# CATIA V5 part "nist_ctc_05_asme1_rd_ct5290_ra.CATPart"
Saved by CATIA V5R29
Part number: CTC_05_ASME1_C29_RC
Revision: C
Nomenclature: Complex Test Case 5
Property "Modeled By": "Rich Eckenrode, RECON-Services.com - Revised by DS"
Property "CAGE Code": "64JW1"
Property "Company": "RECON Services Incorporated"
Bounding box of the stored display mesh (mm): x -263.525 to 263.525, y -279.4 to 279.4, z 0 to 482.6
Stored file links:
  E:\users\dgn\TPS V5\Import-export annotations\Step\PMI representation 2015\NIST UC\CTC\nist_ctc_05_asme1_ct5210_rc - V5R29.CATPart
  E:\users\dgn\TPS V5\Import-export annotations\Step\PMI representation 2015\NIST UC\CTC\nist_ctc_05_asme1_ct5210_rc.CATPart
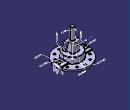
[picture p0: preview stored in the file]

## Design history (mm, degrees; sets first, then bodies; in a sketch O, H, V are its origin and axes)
TTRSSet1
AxisSystem1: origin (0, 0, 0), X (1, 0, 0), Y (0, 1, 0), Z (0, 0, 1)
f4a2d38f3ddc11d3a929006094b99c4b_11 "CATTPSSet"
Set1 "MBD_A"
  Line1: type PtPt, FirstPoint Point2, SecondPoint Point1
  Fill1: Boundary Sketch17
Set2 "MBD_B"
  Fill2: Boundary Sketch18
Body1 (main body)
  Sketch1 on xy-plane, origin (0, 0, 0), H (1, 0, 0), V (0, 1, 0)
    arc A1 centre (0, 0) radius 279.4 from (263.525, 92.8382) to (-263.525, 92.8382) ccw
    line L1 (263.525, 92.8382) -> (263.525, -92.8382)
    line L2 (-263.525, -92.8382) -> (-263.525, 92.8382)
    arc A2 centre (0, 0) radius 279.4 from (-263.525, -92.8382) to (263.525, -92.8382) ccw
    radius A1 = 279.4
    distance L1 L2 = 527.05
    distance L2 V = 263.525
    vertical: L1 V, L2 V
    coincidence: A1 A2
  Pad1: profile Sketch1, direction (0, 0, 1), length 25.4
  Sketch2 on end face of Pad1, origin (0, 0, 25.4), H (1, 0, 0), V (0, 1, 0)
    circle A1 centre (0, 0) radius 152.4
    radius A1 = 152.4
  Pad2: profile Sketch2, direction (0, 0, 1), length 101.6
  Sketch3 on face of Pad1 from Sketch1.L1, origin (263.525, 0, 0), H (0, 1, 0), V (0, 0, 1)
    construction line L1 (0, 195.9632) -> (0, -179.8906)
    point P1 (0, 195.9632)
    construction line L2 (-120.3979, -146.05) -> (120.3979, -146.05)
    arc A1 centre (0, -146.05) radius 203.2 from (69.85, 44.7672) to (32.0282, 54.61) ccw
    point P5 (0, -146.05)
    line L3 (69.85, 44.7672) -> (69.85, 25.4)
    line L4 (-69.85, 44.7672) -> (-69.85, 25.4)
    projected line E1 (-92.8382, 25.4) -> (92.8382, 25.4) from edge [face of Pad1 from Sketch1.L1 | end face of Pad1]
    projected line E2 (-69.85, 25.4) -> (69.85, 25.4) from edge [face of Pad1 from Sketch1.L1 | end face of Pad1]
    line L5 (32.0282, 54.61) -> (-32.0282, 54.61)
    arc A2 centre (0, -146.05) radius 203.2 from (-32.0282, 54.61) to (-69.85, 44.7672) ccw
    distance H L2 = 146.05
    radius A1 = 203.2
    distance L3 L4 = 139.7
    distance L3 L1 = 69.85
    distance L5 E1 = 29.21
    distance P5 L1 = 0
    coincidence: P1 V, A1 A2
    vertical: L1 V, L3 V, L4 V
    horizontal: L2 H, L5 H
    midpoint: P5 L2
  Pad3: profile Sketch3, direction (-1, 0, 0), length 527.05
  Sketch4 on face of Pad3 from Sketch3.L5, origin (0, 0, 54.61), H (1, 0, 0), V (0, 1, 0)
    axis line L1 (333.3573, 0) -> (-349.9817, 0)
    point P1 (333.3573, 0)
    arc A1 centre (203.2, 0) radius 19.05 from (203.2, 19.05) to (203.2, -19.05) ccw
    point P3 (203.2, 0)
    arc A2 centre (-203.2, 0) radius 19.05 from (-203.2, -19.05) to (-203.2, 19.05) ccw
    point P4 (-203.2, 0)
    line L2 (203.2, 19.05) -> (302.0185, 19.05)
    line L3 (302.0185, 19.05) -> (302.0185, -19.05)
    line L4 (302.0185, -19.05) -> (203.2, -19.05)
    line L5 (-203.2, 19.05) -> (-294.9477, 19.05)
    line L6 (-294.9477, 19.05) -> (-294.9477, -19.05)
    line L7 (-294.9477, -19.05) -> (-203.2, -19.05)
    distance L5 L7 = 38.1
    distance L1 L5 = 19.05
    distance V P4 = 203.2
    distance P3 V = 203.2
    coincidence: P1 H, P3 L1, P4 L1, L5 L2, L7 L4
    horizontal: L1 H, L2 H, L4 H, L5 H, L7 H
    vertical: L3 V, L6 V
    tangency: L5 A2, A1 L2
  Pocket1: profile Sketch4, direction (0, 0, -1), length 8.89
  Sketch5 on end face of Pocket1, origin (0, 0, 45.72), H (1, 0, 0), V (0, 1, 0)
    axis line L1 (321.9499, 0) -> (-320.0091, 0)
    point P1 (321.9499, 0)
    reference projected arc E1 centre (203.2, 0) radius 19.05 from (203.2, 19.05) to (203.2, -19.05) ccw from edge [face of Pad3 from Sketch3.L5 | face of Pocket1 from Sketch4.A1]
    point P5 (203.2, 0)
    reference projected arc E2 centre (-203.2, 0) radius 19.05 from (-203.2, -19.05) to (-203.2, 19.05) ccw from edge [face of Pad3 from Sketch3.L5 | face of Pocket1 from Sketch4.A2]
    point P8 (-203.2, 0)
    point P9 (234.95, 0)
    point P10 (-234.95, 0)
    distance P5 P9 = 31.75
    distance P8 P10 = 31.75
    coincidence: P1 H, P9 L1, P10 L1
    horizontal: L1 H
    concentricity: P5 E1, P8 E2
  Sketch6 on end face of Pocket1, origin (234.95, 0, 45.72), H (1, 0, 0), V (0, 1, 0)
    point P1 (0, 0)
    reference projected point E1 (0, 0) from Sketch5.P9
    coincidence: E1 P1
  Hole1: placed by Sketch6, at (234.95, 0, 45.72) direction (0, 0, -1), diameter 7.9375, depth 30.48, V-bottom angle 118, threaded, thread diameter 9.525, thread depth 25.4, pitch 1.5875
  UserPattern1: of Hole1, copies 4, at the points of Sketch5
  Sketch7 on start face of Pad1, origin (0, 0, 0), H (1, 0, 0), V (0, -1, 0)
    circle A1 centre (0, 0) radius 127
    radius A1 = 127
  Pocket2: profile Sketch7, direction (0, 0, 1), length 101.6
  Sketch8 on end face of Pad1, origin (0, 0, 25.4), H (1, 0, 0), V (0, 1, 0)
    construction line L1 (331.5002, 0) -> (-339.96, 0)
    point P1 (331.5002, 0)
    axis line L2 (0, 335.6521) -> (0, -346.3045)
    point P3 (0, 335.6521)
    construction circle A1 centre (0, 0) radius 222.25
    point P5 (0, 222.25)
    point P6 (0, -222.25)
    point P7 (111.1128, -192.4812)
    point P8 (192.4741, -111.125)
    point P9 (-111.1128, -192.4812)
    point P10 (-192.4741, -111.125)
    point P11 (-192.4741, 111.125)
    point P12 (-111.1128, 192.4812)
    point P13 (111.1128, 192.4812)
    point P14 (192.4741, 111.125)
    radius A1 = 222.25
    distance L1 P14 = 111.125
    distance P8 L1 = 111.125
    distance P7 L1 = 192.4812
    distance P13 L1 = 192.4812
    distance P9 L1 = 192.4812
    distance P10 L1 = 111.125
    distance P11 L1 = 111.125
    distance P12 L1 = 192.4812
    coincidence: P1 H, P3 V, P5 A1, P5 L2, P6 A1, P6 L2, P7 A1, P8 A1, P9 A1, P10 A1, P11 A1, P12 A1, P13 A1, P14 A1
    horizontal: L1 H
    vertical: L2 V
  Sketch9 on end face of Pad1, origin (192.4741, -111.125, 25.4), H (1, 0, 0), V (0, 1, 0)
    point P1 (0, 0)
    reference projected point E1 (0, 0) from Sketch8.P8
    coincidence: E1 P1
  Hole2: placed by Sketch9, at (192.4741, -111.125, 25.4) direction (0, 0, -1), diameter 19.05, through (limit type 3), counterbore diameter 38.1, counterbore depth 12.7
  UserPattern2: of Hole2, copies 10, at the points of Sketch8
  Sketch10 on end face of Pad2, origin (0, 0, 127), H (1, 0, 0), V (0, 1, 0)
    construction line L1 (288.441, 0) -> (-310.0968, 0)
    point P1 (288.441, 0)
    construction line L2 (0, 314.4157) -> (0, -361.8834)
    point P3 (0, 314.4157)
    axis line L3 (288.441, -50.8) -> (-310.0968, -50.8)
    arc A1 centre (0, -50.8) radius 127 from (88.9, 39.8961) to (-88.9, 39.8961) ccw
    point P7 (0, -50.8)
    line L4 (88.9, 39.8961) -> (88.9, -84.582)
    line L5 (88.9, -84.582) -> (-88.9, -84.582)
    line L6 (-88.9, -84.582) -> (-88.9, 39.8961)
    distance L3 L1 = 50.8
    distance L5 L1 = 84.582
    distance L4 L6 = 177.8
    distance L4 L2 = 88.9
    radius A1 = 127
    coincidence: P1 H, P3 V, P7 L3, P7 L2
    horizontal: L1 H, L3 H, L5 H
    vertical: L2 V, L4 V, L6 V
  Pad4: profile Sketch10, direction (0, 0, 1), length 152.4
  Sketch11 on end face of Pad4, origin (0, 0, 279.4), H (1, 0, 0), V (0, 1, 0)
    circle A1 centre (0, 0) radius 31.75
    radius A1 = 31.75
  Pad5: profile Sketch11, direction (0, 0, 1), length 203.2
  Draft1: Angle 12.5, Neutral end face of Pad2, PullDir end face of Pad2, SupportToDraft face of Pad4 from Sketch10.L5
  Sketch12 on face of Pad4 from Sketch10.L4, origin (88.9, 0, 0), H (0, 1, 0), V (0, 0, 1)
    line L1 (6.1525, 301.5693) -> (-32.5486, 127)
    reference projected line E1 (-50.7957, 279.4) -> (-84.582, 127) from edge [face of Pad4 from Sketch10.L5 | face of Pad4 from Sketch10.L4]
    reference projected line E2 (-50.7957, 279.4) -> (-84.582, 127) from edge [face of Pad4 from Sketch10.L5 | face of Pad4 from Sketch10.L4]
    projected line E3 (-152.4, 127) -> (152.4, 127) from edge [face of Pad2 from Sketch2.A1 | end face of Pad2]
    projected line E4 (-32.5486, 127) -> (152.4, 127) from edge [face of Pad2 from Sketch2.A1 | end face of Pad2]
    point P2 (152.4, 127)
    line L2 (152.4, 301.5693) -> (6.1525, 301.5693)
    line L3 (152.4, 127) -> (152.4, 301.5693)
    distance E2 L1 = 50.8
    parallelism: E1 L1
    horizontal: L2 H
    vertical: L3 V
    coincidence: P2 L3
  Pocket3: profile Sketch12, direction (-1, 0, 0), length 25.4
  Mirror1: of Pocket3, about yz-plane
  Sketch13 on face of Pad4 from Sketch10.L4, origin (88.9, 0, 0), H (0, 1, 0), V (0, 0, 1)
    construction line L1 (-20.2806, 299.6909) -> (-63.978, 102.5849)
    reference projected line E1 (-50.7957, 279.4) -> (-84.582, 127) from edge [face of Pad4 from Sketch10.L5 | face of Pad4 from Sketch10.L4]
    reference projected line E2 (-50.7957, 279.4) -> (-84.582, 127) from edge [face of Pad4 from Sketch10.L5 | face of Pad4 from Sketch10.L4]
    construction line L2 (322.7204, 0) -> (-306.8109, 0)
    point P3 (322.7204, 0)
    axis line L3 (262.0078, 127) -> (-248.2666, 127)
    point P7 (-48.711, 171.45)
    point P8 (-40.9683, 206.375)
    point P9 (-33.2256, 241.3)
    distance L1 E2 = 25.4
    distance L3 L2 = 127
    distance P7 L3 = 44.45
    distance P8 L3 = 79.375
    distance P9 L3 = 114.3
    parallelism: L1 E1
    coincidence: P3 H, P7 L1, P8 L1, P9 L1
    horizontal: L2 H, L3 H
  Sketch14 on face of Pad4 from Sketch10.L4, origin (88.9, -33.2256, 241.3), H (0, 1, 0), V (0, 0, 1)
    point P1 (0, 0)
    reference projected point E1 (0, 0) from Sketch13.P9
    coincidence: E1 P1
  Hole3: placed by Sketch14, at (88.9, -33.2256, 241.3) direction (-1, 0, 0), diameter 10.7156, depth 30.48, V-bottom angle 118, threaded, thread diameter 12.7, thread depth 25.4, pitch 1.9538
  UserPattern3: of Hole3, copies 3, at the points of Sketch13
  Sketch15 on face of Pad4 from Sketch10.L6, origin (-88.9, 0, 0), H (0, -1, 0), V (0, 0, 1)
    axis line L1 (19.0174, 305.3893) -> (64.5201, 100.1395)
    reference projected line E1 (84.582, 127) -> (50.7957, 279.4) from edge [face of Pad4 from Sketch10.L5 | face of Pad4 from Sketch10.L6]
    reference projected line E2 (84.582, 127) -> (50.7957, 279.4) from edge [face of Pad4 from Sketch10.L5 | face of Pad4 from Sketch10.L6]
    point P3 (48.711, 171.45)
    point P4 (40.9683, 206.375)
    point P5 (33.2256, 241.3)
    reference projected line E3 (-152.4, 127) -> (152.4, 127) from edge [face of Pad2 from Sketch2.A1 | end face of Pad2]
    reference projected line E4 (-152.4, 127) -> (152.4, 127) from edge [face of Pad2 from Sketch2.A1 | end face of Pad2]
    reference projected line E5 (-152.4, 127) -> (152.4, 127) from edge [face of Pad2 from Sketch2.A1 | end face of Pad2]
    distance L1 E2 = 25.4
    distance P5 E3 = 114.3
    distance P4 E4 = 79.375
    distance P3 E5 = 44.45
    parallelism: L1 E1
    coincidence: P3 L1, P4 L1, P5 L1
  Sketch16 on face of Pad4 from Sketch10.L6, origin (-88.9, -33.2256, 241.3), H (0, 1, 0), V (0, 0, -1)
    point P1 (0, 0)
    reference projected point E1 (0, 0) from Sketch15.P5
    coincidence: E1 P1
  Hole4: placed by Sketch16, at (-88.9, -33.2256, 241.3) direction (1, 0, 0), diameter 10.7156, depth 30.48, V-bottom angle 118, threaded, thread diameter 12.7, thread depth 25.4, pitch 1
  UserPattern4: of Hole4, copies 3, at the points of Sketch15
  Chamfer1: length 6.35, angle 45, on end face of Pad5; edge [face of Pad2 from Sketch2.A1 | face of Mirror1]
  Fillet1: radius 6.35, on edge [end face of Pad4 | face of Pad5 from Sketch11.A1]; edge [face of Pad4 from Sketch10.L5 | face of Mirror1]; edge [face of Mirror1 | face of Pad4 from Sketch10.L6]; edge [face of Mirror1 | face of Mirror1] (x2); edge [face of Mirror1 | face of Pad4 from Sketch10.A1]; edge [face of Mirror1 | end face of Pocket3]; edge [face of Mirror1 | face of Pocket3 from Sketch12.L1]; edge [face of Mirror1 | face of Pad4 from Sketch10.L4]; edge [end face of Pad1 | face of Pad2 from Sketch2.A1] (x2); edge [face of Pad2 from Sketch2.A1 | face of Pad3 from Sketch3.L3]; edge [face of Pad2 from Sketch2.A1 | face of Pad3 from Sketch3.A1]; edge [face of Pad2 from Sketch2.A1 | face of Pad3 from Sketch3.L5] (x2); edge [face of Pad3 from Sketch3.A2 | face of Pad2 from Sketch2.A1]; edge [face of Pad3 from Sketch3.L4 | face of Pad2 from Sketch2.A1]; edge [face of Pad2 from Sketch2.A1 | face of Pad3 from Sketch3.L4]; edge [face of Pad2 from Sketch2.A1 | face of Pad3 from Sketch3.A2]; edge [face of Pad3 from Sketch3.A1 | face of Pad2 from Sketch2.A1]; edge [face of Pad3 from Sketch3.L3 | face of Pad2 from Sketch2.A1]; edge [face of Pad3 from Sketch3.L4 | end face of Pad1] (x2); edge [end face of Pad1 | face of Pad3 from Sketch3.L3] (x2)
  Chamfer2: length 9.525, angle 45, on edge [start face of Pad1 | face of Pocket2 from Sketch7.A1]
  Sketch17 on face of Pad3, origin (263.525, 0, 0), H (0, 1, 0), V (0, 0, 1)
    projected line E1 (19.05, 45.72) -> (-19.05, 45.72) from edge [end face of Pocket1 | face of Pad3]
    point P1 (19.05, 45.72)
    line L1 (-25.4, 13.97) -> (25.4, 13.97)
    line L2 (25.4, 13.97) -> (25.4, 45.72)
    line L3 (25.4, 45.72) -> (-25.4, 45.72)
    line L4 (-25.4, 45.72) -> (-25.4, 13.97)
    point P3 (25.4, 45.72)
    distance L4 L2 = 50.8
    distance V L4 = 25.4
    distance L1 P1 = 31.75
    horizontal: L1 H, L3 H
    vertical: L2 V, L4 V
    coincidence: P3 E1, P3 L3, P3 L2
  Sketch18 on face of Pad3, origin (-263.525, 0, 0), H (0, -1, 0), V (0, 0, 1)
    line L1 (-25.4, 13.97) -> (25.4, 13.97)
    line L2 (25.4, 13.97) -> (25.4, 45.72)
    line L3 (25.4, 45.72) -> (-25.4, 45.72)
    line L4 (-25.4, 45.72) -> (-25.4, 13.97)
    point P1 (25.4, 13.97)
    reference projected line E1 (-19.05, 45.72) -> (19.05, 45.72) from edge [face of Pad3 | end face of Pocket1]
    distance E1 L3 = 0
    distance L3 L1 = 31.75
    distance L2 L4 = 50.8
    distance V L4 = 25.4
    horizontal: L1 H, L3 H
    vertical: L2 V, L4 V
    coincidence: P1 L2, P1 L1
  Point1: (0, 76.2, 266.7)
  Point2: (0, 76.2, 228.6)
  Point3: type Center, Curve edge [start face of Pad1 | face of Chamfer2]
